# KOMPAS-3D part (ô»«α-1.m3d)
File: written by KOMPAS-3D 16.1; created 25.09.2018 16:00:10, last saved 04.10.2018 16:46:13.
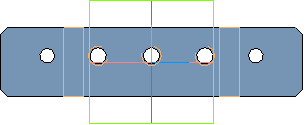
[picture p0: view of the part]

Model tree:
1. Эскиз:3
2. Операция выдавливания:1
     Расстояние 1 = 122
3. Эскиз:4
4. Вырезать элемент выдавливания:1
     Расстояние 1 = 25
5. Условное изображение резьбы:1  (labels: M8)
     Длина резьбы = 25; Шаг резьбы = 1.25; Номинальный диаметр резьбы = 8
6. Подгонка:1
7. Условное изображение резьбы:2  (labels: M8)
     Длина резьбы = 25; Шаг резьбы = 1.25; Номинальный диаметр резьбы = 8
8. Подгонка:2
9. Условное изображение резьбы:4  (labels: M8)
     Длина резьбы = 25; Шаг резьбы = 1.25; Номинальный диаметр резьбы = 8
10. Подгонка:4
11. Фаска:1
     Угол = 45; Длина 1 = 1.6; Длина 2 = 1.6
12. Фаска:2
     Угол = 45; Длина 1 = 3; Длина 2 = 3
13. Эскиз:5
14. Вырезать элемент выдавливания:2
     Расстояние 1 = 28; На расстояние 1 = 8
15. Зеркальный массив:1
16. Экземпляр ( 1 )
17. Экземпляр ( 2 )  (with: Вырезать элемент выдавливания:2)
18. Эскиз:6
19. Вырезать элемент выдавливания:3
     Расстояние 1 = 28; На расстояние 1 = 8
20. Условное изображение резьбы:3  (labels: M8)
     Длина резьбы = 28; Шаг резьбы = 1.25; Номинальный диаметр резьбы = 8
21. Подгонка:3
22. Фаска:3
     Угол = 45; Длина 1 = 1.6; Длина 2 = 1.6
23. Зеркальный массив:2  (with: Экземпляр ( 1 ), Экземпляр ( 2 ), Вырезать элемент выдавливания:3)
24. Фаска:3
25. Эскиз:7
26. Операция выдавливания:2
     Расстояние 1 = 122; Расстояние 2 = 4
27. Фаска:4
     Угол = 45; Длина 1 = 1.5; Длина 2 = 1.5
28. Сечение поверхностью:1  (labels: Сталь 20  ГОСТ 1050-2013; А302-01.05.014)

Expressions: v128/2; v126/2; 21.5*2
Referenced files in C:\Program Files\ASCON\KOMPAS-3D V16\Sys\Thread\: cil0_8724-2002 coarse.xml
